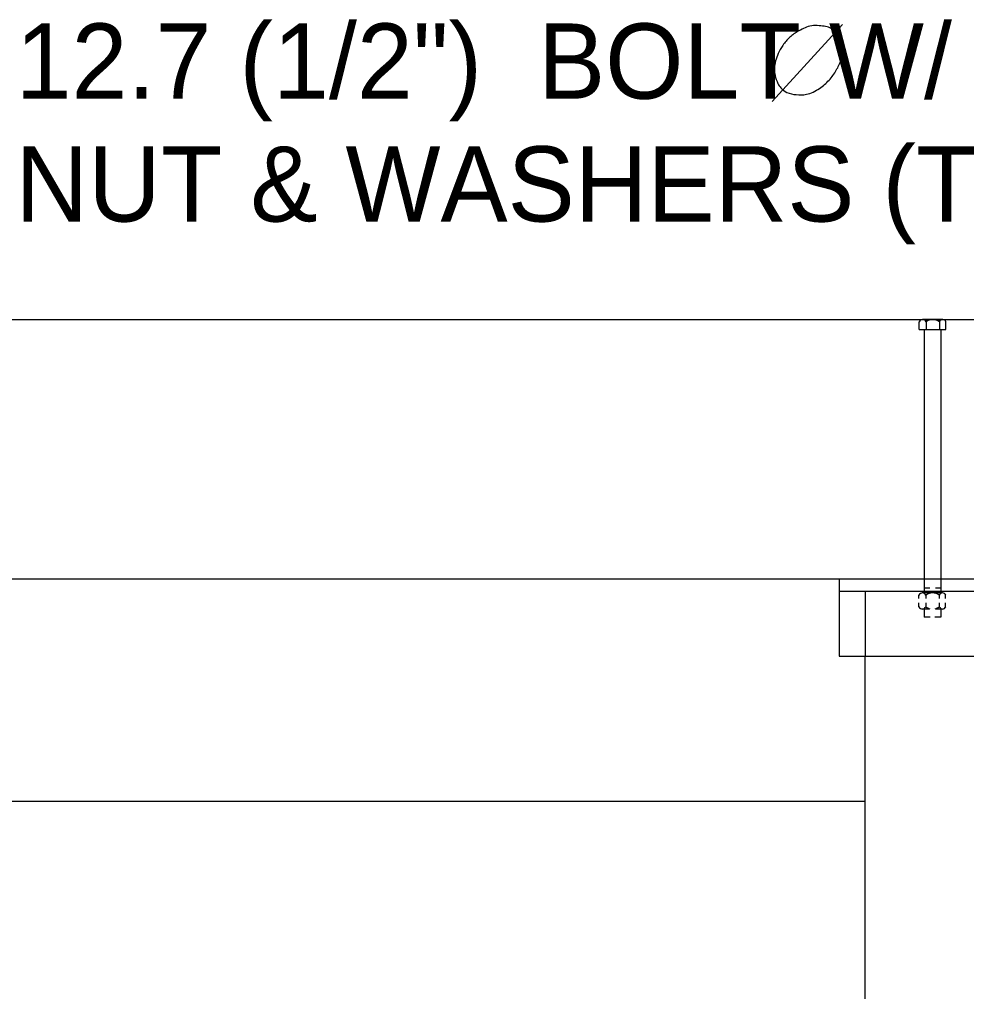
# Model space of a CAD drawing. Extents: x 635440 to 640306, y 296653 to 298484.
# Drawn here: x 639538.91 to 639576.66, y 296815 to 296853.75 of the extents above; entities that cross this region are included whole.
import ezdxf

# ---------------------------------------------------------------- set-up
doc = ezdxf.new("R2010")
doc.units = 0
for name, color, linetype in [('3', 7, 'Continuous'), ('4', 7, 'Continuous'), ('5', 7, 'Continuous'), ('8', 7, 'Continuous')]:
    doc.layers.add(name, color=color, linetype=linetype)

msp = doc.modelspace()

# ---------------------------------------------------------------- linework, layer by layer
at = {"layer": '3'}
for p, q in [((639462.248, 296841.786), (639618.976, 296841.786)), ((639574.772, 296841.388), (639574.772, 296841.692)), ((639575.714, 296841.786), (639574.905, 296841.786)), ((639574.951, 296841.782), (639574.951, 296841.782)), ((639574.966, 296841.782), (639574.966, 296841.782)), ((639574.98, 296841.782), (639574.98, 296841.782)), ((639574.987, 296841.767), (639574.987, 296841.767)), ((639574.995, 296841.782), (639574.995, 296841.782)), ((639575.003, 296841.767), (639575.003, 296841.767)), ((639575.01, 296841.782), (639575.01, 296841.782)), ((639575.01, 296841.753), (639575.01, 296841.753)), ((639575.018, 296841.767), (639575.018, 296841.767)), ((639575.024, 296841.782), (639575.024, 296841.782)), ((639575.024, 296841.753), (639575.024, 296841.753)), ((639575.033, 296841.767), (639575.033, 296841.767)), ((639575.033, 296841.738), (639575.033, 296841.738)), ((639575.039, 296841.782), (639575.039, 296841.782)), ((639575.039, 296841.753), (639575.039, 296841.753)), ((639575.039, 296841.724), (639575.039, 296841.724)), ((639575.047, 296841.767), (639575.047, 296841.767)), ((639575.047, 296841.738), (639575.047, 296841.738)), ((639575.047, 296841.709), (639575.047, 296841.709)), ((639575.047, 296841.692), (639575.047, 296841.388)), ((639575.055, 296841.782), (639575.055, 296841.782)), ((639575.055, 296841.753), (639575.055, 296841.753)), ((639575.055, 296841.724), (639575.055, 296841.724)), ((639575.062, 296841.767), (639575.062, 296841.767)), ((639575.062, 296841.738), (639575.062, 296841.738)), ((639575.062, 296841.709), (639575.062, 296841.709)), ((639575.068, 296841.782), (639575.068, 296841.782)), ((639575.068, 296841.753), (639575.068, 296841.753)), ((639575.068, 296841.724), (639575.068, 296841.724)), ((639575.076, 296841.767), (639575.076, 296841.767)), ((639575.076, 296841.738), (639575.076, 296841.738)), ((639575.083, 296841.782), (639575.083, 296841.782)), ((639575.083, 296841.753), (639575.083, 296841.753)), ((639575.083, 296841.724), (639575.083, 296841.724)), ((639575.091, 296841.767), (639575.091, 296841.767)), ((639575.091, 296841.738), (639575.091, 296841.738)), ((639575.099, 296841.782), (639575.099, 296841.782)), ((639575.099, 296841.753), (639575.099, 296841.753)), ((639575.105, 296841.767), (639575.105, 296841.767)), ((639575.105, 296841.738), (639575.105, 296841.738)), ((639575.114, 296841.782), (639575.114, 296841.782)), ((639575.114, 296841.753), (639575.114, 296841.753)), ((639575.12, 296841.767), (639575.12, 296841.767)), ((639575.128, 296841.782), (639575.128, 296841.782)), ((639575.128, 296841.753), (639575.128, 296841.753)), ((639575.135, 296841.767), (639575.135, 296841.767)), ((639575.143, 296841.782), (639575.143, 296841.782)), ((639575.143, 296841.753), (639575.143, 296841.753)), ((639575.149, 296841.767), (639575.149, 296841.767)), ((639575.158, 296841.782), (639575.158, 296841.782)), ((639575.164, 296841.767), (639575.164, 296841.767)), ((639575.172, 296841.782), (639575.172, 296841.782)), ((639575.18, 296841.767), (639575.18, 296841.767)), ((639575.187, 296841.782), (639575.187, 296841.782)), ((639575.201, 296841.782), (639575.201, 296841.782)), ((639575.216, 296841.782), (639575.216, 296841.782)), ((639575.233, 296841.782), (639575.233, 296841.782)), ((639575.245, 296841.782), (639575.245, 296841.782)), ((639575.378, 296841.782), (639575.378, 296841.782)), ((639575.393, 296841.782), (639575.393, 296841.782)), ((639575.41, 296841.782), (639575.41, 296841.782)), ((639575.422, 296841.782), (639575.422, 296841.782)), ((639575.439, 296841.782), (639575.439, 296841.782)), ((639575.445, 296841.767), (639575.445, 296841.767)), ((639575.453, 296841.782), (639575.453, 296841.782)), ((639575.46, 296841.767), (639575.46, 296841.767)), ((639575.468, 296841.782), (639575.468, 296841.782)), ((639575.474, 296841.767), (639575.474, 296841.767)), ((639575.483, 296841.782), (639575.483, 296841.782)), ((639575.483, 296841.753), (639575.483, 296841.753)), ((639575.491, 296841.767), (639575.491, 296841.767)), ((639575.497, 296841.782), (639575.497, 296841.782)), ((639575.497, 296841.753), (639575.497, 296841.753)), ((639575.503, 296841.767), (639575.503, 296841.767)), ((639575.512, 296841.782), (639575.512, 296841.782)), ((639575.512, 296841.753), (639575.512, 296841.753)), ((639575.518, 296841.767), (639575.518, 296841.767)), ((639575.518, 296841.738), (639575.518, 296841.738)), ((639575.526, 296841.782), (639575.526, 296841.782)), ((639575.526, 296841.753), (639575.526, 296841.753)), ((639575.535, 296841.767), (639575.535, 296841.767)), ((639575.535, 296841.738), (639575.535, 296841.738)), ((639575.541, 296841.782), (639575.541, 296841.782)), ((639575.541, 296841.753), (639575.541, 296841.753)), ((639575.541, 296841.724), (639575.541, 296841.724)), ((639575.549, 296841.767), (639575.549, 296841.767)), ((639575.549, 296841.738), (639575.549, 296841.738)), ((639575.555, 296841.782), (639575.555, 296841.782)), ((639575.555, 296841.753), (639575.555, 296841.753)), ((639575.555, 296841.724), (639575.555, 296841.724)), ((639575.564, 296841.767), (639575.564, 296841.767)), ((639575.564, 296841.738), (639575.564, 296841.738)), ((639575.564, 296841.709), (639575.564, 296841.709)), ((639575.57, 296841.782), (639575.57, 296841.782)), ((639575.57, 296841.753), (639575.57, 296841.753)), ((639575.57, 296841.724), (639575.57, 296841.724)), ((639575.578, 296841.767), (639575.578, 296841.767)), ((639575.578, 296841.738), (639575.578, 296841.738)), ((639575.578, 296841.709), (639575.578, 296841.709)), ((639575.58, 296841.767), (639575.58, 296841.767)), ((639575.58, 296841.738), (639575.58, 296841.738)), ((639575.58, 296841.709), (639575.58, 296841.709)), ((639575.58, 296841.692), (639575.58, 296841.388)), ((639575.589, 296841.782), (639575.589, 296841.782)), ((639575.589, 296841.753), (639575.589, 296841.753)), ((639575.589, 296841.724), (639575.589, 296841.724)), ((639575.595, 296841.767), (639575.595, 296841.767)), ((639575.595, 296841.738), (639575.595, 296841.738)), ((639575.603, 296841.782), (639575.603, 296841.782)), ((639575.603, 296841.753), (639575.603, 296841.753)), ((639575.61, 296841.767), (639575.61, 296841.767)), ((639575.618, 296841.782), (639575.618, 296841.782)), ((639575.618, 296841.753), (639575.618, 296841.753)), ((639575.624, 296841.767), (639575.624, 296841.767)), ((639575.633, 296841.782), (639575.633, 296841.782)), ((639575.641, 296841.767), (639575.641, 296841.767)), ((639575.647, 296841.782), (639575.647, 296841.782)), ((639575.662, 296841.782), (639575.662, 296841.782)), ((639575.676, 296841.782), (639575.676, 296841.782)), ((639575.837, 296841.388), (639575.837, 296841.692)), ((639574.772, 296841.388), (639575.837, 296841.388)), ((639574.976, 296841.388), (639574.976, 296830.892)), ((639575.633, 296841.388), (639575.633, 296830.892)), ((639462.248, 296831.45), (639618.976, 296831.45)), ((639571.589, 296831.45), (639571.589, 296828.375)), ((639574.762, 296830.665), (639574.762, 296830.798)), ((639575.705, 296830.892), (639574.895, 296830.892)), ((639575.199, 296831.073), (639574.976, 296831.073)), ((639575.039, 296830.798), (639575.039, 296830.665)), ((639575.633, 296831.073), (639575.425, 296831.073)), ((639575.572, 296830.798), (639575.572, 296830.665)), ((639575.828, 296830.665), (639575.828, 296830.798)), ((639574.762, 296830.34), (639574.762, 296830.496)), ((639575.039, 296830.496), (639575.039, 296830.34)), ((639575.572, 296830.496), (639575.572, 296830.34)), ((639575.828, 296830.34), (639575.828, 296830.496)), ((639575.172, 296830.246), (639574.895, 296830.246)), ((639574.976, 296830.246), (639574.976, 296829.925)), ((639575.705, 296830.246), (639575.436, 296830.246)), ((639575.633, 296830.246), (639575.633, 296829.925)), ((639575.214, 296829.925), (639574.976, 296829.925)), ((639575.633, 296829.925), (639575.394, 296829.925)), ((639571.589, 296828.375), (639583.968, 296828.375)), ((639572.612, 296828.375), (639572.612, 296784.629)), ((639529.791, 296822.591), (639572.612, 296822.591))]:
    msp.add_line(p, q, dxfattribs=at)
for centre, radius, start, end in [((639574.91, 296841.638), 0.148, 88.1729, 158.7131), ((639574.91, 296841.638), 0.148, 21.2869, 88.1729), ((639575.315, 296841.362), 0.424, 51.05, 128.95), ((639575.71, 296841.652), 0.135, 17.4518, 162.5482), ((639574.901, 296830.744), 0.148, 88.1729, 158.7131), ((639574.901, 296830.744), 0.148, 21.2869, 88.1729), ((639575.305, 296830.468), 0.424, 51.05, 128.95), ((639575.701, 296830.757), 0.135, 17.4518, 162.5482), ((639574.901, 296830.394), 0.148, 201.2869, 271.8271), ((639574.901, 296830.394), 0.148, 271.8271, 338.7131), ((639575.305, 296830.67), 0.424, 231.05, 256.0077), ((639575.305, 296830.67), 0.424, 284.3427, 308.95), ((639575.701, 296830.381), 0.135, 197.4518, 342.5482)]:
    msp.add_arc(centre, radius, start, end, dxfattribs=at)
at = {"layer": '5'}
msp.add_line((639568.918, 296850.48), (639571.718, 296853.545), dxfattribs=at)
msp.add_spline([(639571.426, 296853.243), (639571.207, 296853.414), (639570.989, 296853.474), (639570.714, 296853.499), (639570.557, 296853.499), (639570.289, 296853.437), (639570.043, 296853.324), (639569.87, 296853.226), (639569.539, 296852.962), (639569.28, 296852.624), (639569.124, 296852.307), (639569.032, 296852.018), (639569.005, 296851.749), (639569.032, 296851.518), (639569.145, 296851.189), (639569.263, 296851.018), (639569.505, 296850.837), (639569.868, 296850.749), (639570.28, 296850.762), (639570.801, 296850.999), (639571.182, 296851.326), (639571.47, 296851.724), (639571.657, 296852.139), (639571.72, 296852.599), (639571.639, 296852.895), (639571.439, 296853.243)], degree=3, dxfattribs=at)
at = {"layer": '8'}
for p, q in [((639571.589, 296830.959), (639583.968, 296830.959)), ((639572.614, 296830.959), (639572.614, 296828.375))]:
    msp.add_line(p, q, dxfattribs=at)

# ---------------------------------------------------------------- texts
at = {"layer": '4'}
for s, p in [('12.7 (1/2")  BOLT W/ STD.', (639538.758, 296850.587)), ('NUT & WASHERS (TYP.)', (639538.758, 296845.69))]:
    msp.add_text(s, height=3.00014, dxfattribs=at).set_placement(p)

doc.saveas('drawing.dxf')
